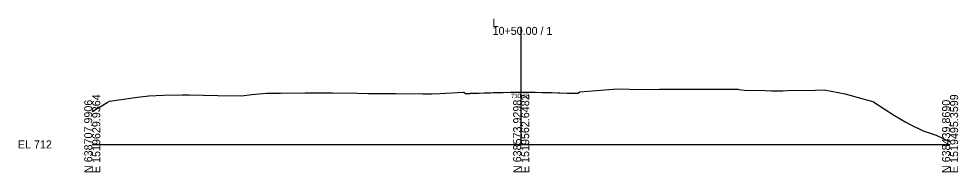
# Model space of a CAD drawing. Extents: x -26 to 3903, y -10 to 9531.
# Drawn here: x -25.7 to 302.8, y 490.3 to 543.9 of the extents above; entities that cross this region are included whole.
import ezdxf

# ---------------------------------------------------------------- set-up
doc = ezdxf.new("R2010")
doc.units = 0
for name, color, linetype in [('Default', 7, 'Continuous'), ('Exist Cross Section Cell', 7, 'Continuous'), ('Exist XS Center Line Elevation Label', 7, 'Continuous'), ('Exist XS Ground Line', 7, 'Continuous')]:
    doc.layers.add(name, color=color, linetype=linetype)

msp = doc.modelspace()

# ---------------------------------------------------------------- linework, layer by layer
at = {"layer": 'Exist Cross Section Cell'}
for p, q in [((150, 500), (150, 541.05)), ((0, 500), (150, 500)), ((150, 500), (300, 500))]:
    msp.add_line(p, q, dxfattribs=at)
at = {"layer": 'Exist XS Ground Line'}
msp.add_lwpolyline([(0, 511.45), (3.66, 513.68), (5.21, 514.66), (5.99, 515.14), (15.81, 516.53), (18.85, 516.9), (19.84, 517.01), (24.91, 517.17), (31.39, 517.31), (33.93, 517.37), (43.91, 517.04), (52.17, 516.94), (55.82, 517.48), (60.92, 517.87), (62.4, 517.86), (65.89, 517.84), (74.42, 517.98), (78.54, 518.03), (84.03, 517.96), (92.74, 517.88), (96.32, 517.83), (106.02, 517.82), (115.63, 517.68), (118.61, 517.63), (121.56, 517.81), (129.88, 518.26), (129.9, 518.25), (130.56, 517.76), (132.06, 517.83), (132.32, 517.85), (132.67, 517.85), (135.09, 517.92), (135.3, 517.92), (137.09, 517.98), (138.1, 518.01), (139.26, 518.05), (140.15, 518.09), (140.79, 518.09), (140.89, 518.09), (141.14, 518.09), (143.68, 518.16), (146.21, 518.22), (146.46, 518.22), (146.72, 518.23), (149.26, 518.26), (149.96, 518.28), (150.05, 518.28), (151.91, 518.26), (152.07, 518.26), (153.86, 518.24), (154.89, 518.23), (157.35, 518.18), (157.66, 518.17), (157.93, 518.17), (160.03, 518.13), (160.17, 518.13), (160.66, 518.12), (162.93, 518.05), (163.25, 518.05), (163.57, 518.03), (166.04, 517.95), (166.74, 517.92), (167.61, 517.89), (168, 517.87), (169.73, 517.84), (169.87, 517.84), (170.43, 518.27), (170.52, 518.33), (179.27, 519.05), (183.56, 519.41), (187.83, 519.31), (193.48, 519.21), (198.37, 519.33), (207.97, 519.27), (223.31, 519.24), (225.93, 519.25), (226.17, 519.2), (228.09, 518.91), (235.35, 518.77), (237.59, 518.66), (240.54, 518.73), (241.48, 518.75), (243.17, 518.78), (252.82, 518.95), (255.94, 519.03), (263.36, 517.69), (267.86, 516.37), (273.28, 514.83), (273.32, 514.82), (273.34, 514.8), (280.51, 510.1), (284.57, 507.8), (286.09, 507), (290.61, 504.76), (295.1, 503.22), (300, 500.96)], dxfattribs=at)

# ---------------------------------------------------------------- texts
at = {"layer": 'Default'}
msp.add_text('-', height=0.0001, dxfattribs=at).set_placement((0, 500))
at = {"layer": 'Exist Cross Section Cell'}
for s, p in [('L', (140, 541.05)), ('10+50.00 / 1', (140, 538.25)), ('EL 712', (-26, 498.6))]:
    msp.add_text(s, height=2.8, dxfattribs=at).set_placement(p)
for s, p in [('E 1519629.9364', (2.8, 490)), ('E 1519562.6482', (152.8, 490)), ('E 1519495.3599', (302.8, 490)), ('N 638707.9906', (0, 490)), ('N 638573.9298', (150, 490)), ('N 638439.8690', (300, 490))]:
    msp.add_text(s, height=2.8, rotation=90, dxfattribs=at).set_placement(p)
at = {"layer": 'Exist XS Center Line Elevation Label'}
msp.add_text('730.28', height=1.5, rotation=0.8401, dxfattribs=at).set_placement((146.43, 516.16))

doc.saveas('drawing.dxf')
